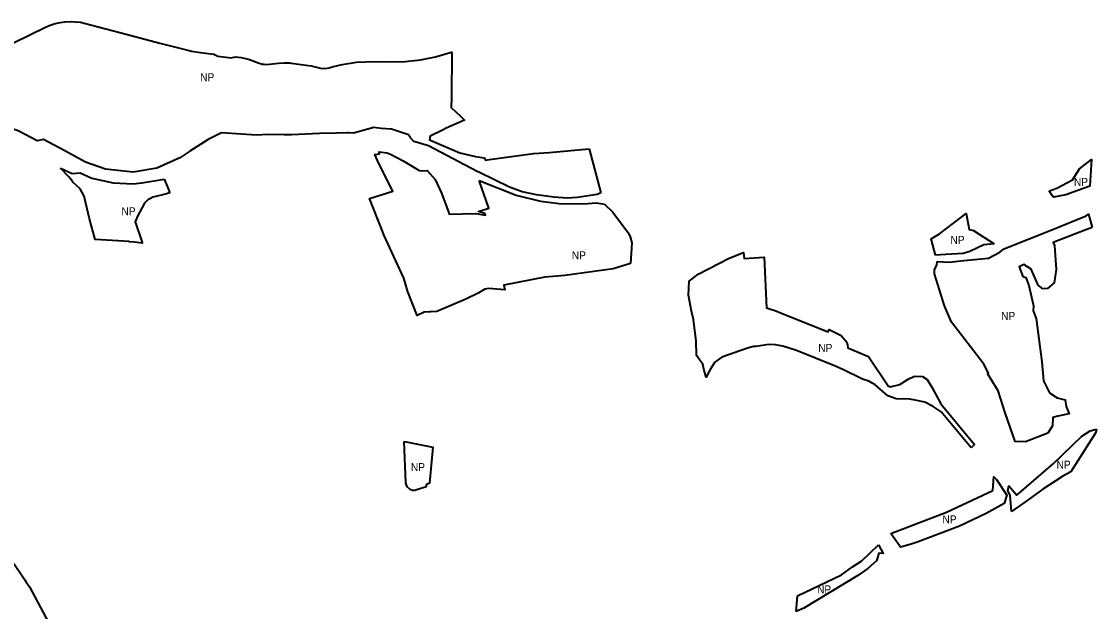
# Model space of a CAD drawing. Extents: x -650971 to -642489, y -1074311 to -1062745.
# Drawn here: x -645155 to -643544, y -1069701 to -1068817 of the extents above; entities that cross this region are included whole.
import ezdxf

# ---------------------------------------------------------------- set-up
doc = ezdxf.new("R2010")
doc.units = 0
doc.header["$LTSCALE"] = 4.8
for name, color, linetype, lineweight in [('24', 7, 'Continuous', 35), ('48', 7, 'Continuous', 35), ('62', 7, 'Continuous', 35)]:
    doc.layers.add(name, color=color, linetype=linetype, lineweight=lineweight)

msp = doc.modelspace()

# ---------------------------------------------------------------- linework, layer by layer
at = {"layer": '24'}
msp.add_lwpolyline([(-645166.67, -1069629), (-645153.33, -1069649.24), (-645150.3, -1069653.84), (-645148.8, -1069656.1), (-645143.56, -1069664.05), (-645118.98, -1069710.08), (-645095.1, -1069757.62), (-645063.26, -1069825.99), (-645051.78, -1069854.2), (-645043.5, -1069878.37), (-645032.85, -1069912.07), (-645024.45, -1069944.43), (-645018.28, -1069967.49)], dxfattribs=at)
at = {"layer": '48'}
for points in [[(-645212.72, -1068870.49), (-645119.5, -1068825.24), (-645112.38, -1068822.16), (-645104.87, -1068819.7), (-645097.47, -1068817.98), (-645090.01, -1068816.92), (-645082.34, -1068816.52), (-645074.66, -1068816.8), (-645067.04, -1068817.76), (-645059.46, -1068819.41), (-644998.7, -1068835.48), (-644947.96, -1068848.91), (-644906.18, -1068859.57), (-644900.37, -1068860.89), (-644883.44, -1068863.56), (-644867.05, -1068865.58), (-644861.04, -1068868.43), (-644840.86, -1068870.9), (-644834.48, -1068869.6), (-644826.24, -1068870.62), (-644819.79, -1068871.79), (-644813.52, -1068873.69), (-644799.27, -1068878.92), (-644795.57, -1068880.03), (-644794.33, -1068880.25), (-644791.66, -1068880.72), (-644787.7, -1068880.94), (-644783.84, -1068880.69), (-644770.17, -1068879.01), (-644761.63, -1068878.43), (-644753.71, -1068878.41), (-644751.36, -1068878.76), (-644721.29, -1068883.2), (-644707.32, -1068886.63), (-644700.83, -1068886.97), (-644694.39, -1068886.08), (-644689.63, -1068884.43), (-644674.5, -1068880.97), (-644653.09, -1068877.33), (-644626.34, -1068876.48), (-644602.97, -1068877.11), (-644580.06, -1068876.69), (-644557.21, -1068874.19), (-644534.67, -1068869.62), (-644512.71, -1068863.06), (-644510.37, -1068861.95)], [(-644510.37, -1068861.95), (-644510.75, -1068931.16), (-644511.47, -1068945.37), (-644503.61, -1068952.56), (-644498.8, -1068956.97), (-644496.63, -1068959.11), (-644491.31, -1068964.35), (-644514.16, -1068974.62), (-644519.61, -1068977.02), (-644523.4, -1068978.98), (-644543.05, -1068988.64), (-644544.02, -1068993.75), (-644498.28, -1069013.19), (-644475.09, -1069018.99), (-644461.74, -1069020.83), (-644459.67, -1069024.41), (-644453.95, -1069023.63), (-644387.91, -1069014.64), (-644364.53, -1069012.83), (-644304.6, -1069007.55)], [(-644952.47, -1069036.35), (-644988.11, -1069042.51), (-645029.47, -1069037.71), (-645059.3, -1069027.45), (-645090.35, -1069010.56), (-645122.25, -1068993.21), (-645131.73, -1068995.69), (-645159.37, -1068981.11), (-645189.84, -1068969.91), (-645218.85, -1068964.3), (-645232.4, -1068961.67), (-645255.21, -1068962.49), (-645275.45, -1068964.38), (-645292.77, -1068966.91), (-645311.99, -1068972.74), (-645328.55, -1068980.37), (-645350.17, -1068993.33), (-645371.56, -1069010.81), (-645396.53, -1069030.88), (-645413.29, -1069042.92)], [(-644803.31, -1068986.97), (-644855.56, -1068983.38), (-644875.57, -1068993.47), (-644903.21, -1069010.69), (-644918.04, -1069020.91), (-644952.47, -1069036.35)], [(-644657.61, -1068983.91), (-644665.41, -1068983.39), (-644667.57, -1068983.47), (-644683, -1068984.03), (-644708.6, -1068984.54), (-644750.67, -1068986.34), (-644761.88, -1068986.27), (-644785.78, -1068986.13), (-644803.31, -1068986.97)], [(-644572.05, -1068991.08), (-644575.29, -1068986.48), (-644600.67, -1068977.77), (-644616.36, -1068976.86), (-644627.41, -1068975.6), (-644657.61, -1068983.91)], [(-644286.94, -1069073.19), (-644292.27, -1069076.05), (-644319.2, -1069079.82), (-644322.55, -1069080.62), (-644337.6, -1069081.29), (-644357.4, -1069079.84), (-644383.55, -1069076.57), (-644404.96, -1069071.76), (-644424.01, -1069065.01), (-644468.95, -1069043.11), (-644472.37, -1069041.44), (-644545.54, -1069003.12), (-644567.09, -1068996.26), (-644572.05, -1068991.08)], [(-644614.41, -1069131.08), (-644633.66, -1069082), (-644598.81, -1069071.02), (-644619.54, -1069029.55), (-644625.69, -1069015.84), (-644618.8, -1069014.7), (-644619.1, -1069011.81), (-644607.16, -1069013.56), (-644601.43, -1069015.74), (-644583.05, -1069025.29), (-644563.19, -1069037.21), (-644558.56, -1069039.86), (-644553.62, -1069040.53), (-644547.31, -1069040.11), (-644535.13, -1069053.18), (-644525.83, -1069073.84), (-644515.07, -1069103.52), (-644514.47, -1069105.62), (-644474.33, -1069104.22), (-644459.82, -1069106.73), (-644461.01, -1069104.36), (-644470.37, -1069101.55), (-644454.75, -1069096.51), (-644469.28, -1069054.8)], [(-644304.6, -1069007.55), (-644293.51, -1069049.01), (-644286.94, -1069073.19)], [(-645096.97, -1069036.63), (-645079.65, -1069044.32), (-645067.65, -1069043.18), (-645049.91, -1069051.48), (-645017.77, -1069058.35), (-644987.99, -1069059.67), (-644975.19, -1069058.65), (-644941.27, -1069052.9)], [(-645080.589, -1069054.473), (-645084.19, -1069049.55), (-645096.97, -1069036.63)], [(-643614.82, -1069070.45), (-643614.36, -1069070.29), (-643603.72, -1069066.5), (-643580.21, -1069053.96), (-643569.44, -1069037.24), (-643551.72, -1069023.19), (-643554.17, -1069063.59)], [(-644932.95, -1069073.65), (-644943.69, -1069076.34), (-644958.25, -1069079.99), (-644962.15, -1069081.85), (-644965.95, -1069083.67), (-644970.84, -1069088.8), (-644981.3, -1069108.22), (-644985.15, -1069116.67), (-644974.34, -1069147.85), (-644974.505, -1069149.05), (-644986.221, -1069147.139), (-644994.006, -1069146.673), (-644993.99, -1069146.57), (-645044.97, -1069143.38), (-645053.61, -1069112.32), (-645061.2, -1069078.47), (-645067.57, -1069067.16), (-645078.47, -1069057.37), (-645080.589, -1069054.473)], [(-644941.27, -1069052.9), (-644937.05, -1069063.4), (-644932.95, -1069073.65)], [(-644469.28, -1069054.8), (-644414.04, -1069076.75), (-644377.36, -1069085.89), (-644349.32, -1069089.22), (-644331.44, -1069090), (-644306.29, -1069089.37), (-644293.62, -1069088.17), (-644281.26, -1069090.19)], [(-643554.17, -1069063.59), (-643589.94, -1069076.36), (-643608.65, -1069080.11), (-643610.31, -1069077.52), (-643614.82, -1069070.45)], [(-644281.26, -1069090.19), (-644269.11, -1069102.31), (-644245.65, -1069133.66), (-644243.14, -1069139.47), (-644240.67, -1069148.58), (-644242.48, -1069179.49)], [(-643785.6, -1069166.98), (-643792.04, -1069142.27), (-643784.55, -1069137.77), (-643779.31, -1069134.63), (-643747.75, -1069110.71), (-643739.66, -1069104.58), (-643734.75, -1069128.3), (-643728.49, -1069129.95), (-643697.29, -1069149.7)], [(-643782.92, -1069176.24), (-643764.86, -1069177.58), (-643743.11, -1069175.08), (-643705.7, -1069171.37), (-643688.91, -1069162.16), (-643683.68, -1069157.86), (-643681.63, -1069157.04), (-643610.81, -1069129.04), (-643559.5, -1069107.98), (-643555.98, -1069105.57), (-643550.79, -1069125.24)], [(-644470.64, -1069224), (-644489.27, -1069233.04), (-644532.71, -1069251.12), (-644541.83, -1069251.66), (-644543.88, -1069251.78), (-644552.01, -1069252.24), (-644562.47, -1069257.56), (-644576.08, -1069221.66), (-644582.29, -1069201.27), (-644612.3, -1069136.45), (-644614.41, -1069131.08)], [(-643550.79, -1069125.24), (-643559.88, -1069129.05), (-643609.08, -1069147.64), (-643607.02, -1069152.34)], [(-643697.29, -1069149.7), (-643712.74, -1069151.46), (-643733.83, -1069161.46), (-643743.99, -1069164.43), (-643769.71, -1069166.04), (-643785.6, -1069166.98)], [(-644143.54, -1069317.05), (-644144.05, -1069295.67), (-644148.22, -1069263.22), (-644151.11, -1069250.7), (-644155.37, -1069226.72), (-644154.36, -1069206.06), (-644141.24, -1069195.17), (-644094.79, -1069171.27), (-644073.35, -1069162.84), (-644071.97, -1069171.72), (-644042.37, -1069169.77), (-644038.83, -1069245.65), (-644024.93, -1069250.23), (-644015.12, -1069254.24), (-643946.16, -1069281.84), (-643944.89, -1069278.32), (-643926.74, -1069287.37), (-643918.08, -1069297.33), (-643917.36, -1069302.04), (-643916.78, -1069305.89), (-643885.63, -1069318.72), (-643856.43, -1069362.68), (-643853.56, -1069364.44), (-643838.69, -1069360.79), (-643826.21, -1069352.92), (-643817.06, -1069348.14), (-643804.83, -1069348.99), (-643798.1, -1069353.51), (-643791.02, -1069364.54), (-643777.27, -1069389.71), (-643726.74, -1069450.72), (-643731.98, -1069455.66)], [(-643607.02, -1069152.34), (-643604.38, -1069188.48), (-643607.37, -1069208.43), (-643617.64, -1069217), (-643624.38, -1069217.27), (-643631.66, -1069211.67), (-643641.84, -1069187.68), (-643653.05, -1069180.98), (-643660.22, -1069184.11), (-643654.57, -1069198.77), (-643649.84, -1069200.4), (-643645.61, -1069212.25), (-643638.72, -1069242.94), (-643639.23, -1069250.38), (-643634.56, -1069262.02), (-643625.9, -1069326.77), (-643623.28, -1069355.47), (-643614.35, -1069373.28), (-643602.92, -1069380.53), (-643590.89, -1069383.9), (-643589.52, -1069393.88), (-643585.19, -1069404.76), (-643601.9, -1069408.43), (-643609.6, -1069409.99), (-643610.18, -1069422.91), (-643616.78, -1069433.81), (-643650.28, -1069446.91), (-643665.87, -1069446.1), (-643681.09, -1069403.24), (-643691.6, -1069370.3), (-643707.23, -1069344.52)], [(-644242.48, -1069179.49), (-644268.7, -1069187.42), (-644340.83, -1069197.13), (-644371.08, -1069199.84), (-644432.53, -1069212.02), (-644430.91, -1069218.82), (-644454.87, -1069217.05), (-644460.97, -1069217.61), (-644470.64, -1069224)], [(-643707.23, -1069344.52), (-643705.74, -1069343.54), (-643712.78, -1069330.24), (-643761.21, -1069267.12), (-643771.86, -1069242.77), (-643786.89, -1069195.02), (-643786.97, -1069188.11), (-643783.2, -1069181.85), (-643782.92, -1069176.24)], [(-643731.98, -1069455.66), (-643776.78, -1069401.87), (-643788.63, -1069393.7), (-643801.36, -1069387.23), (-643815.93, -1069384.23), (-643823.72, -1069382.61), (-643844.28, -1069382.26), (-643856.58, -1069377.59), (-643876.34, -1069360.61), (-643879.48, -1069359.13), (-643885.22, -1069355.58), (-643894.84, -1069352.76), (-643924.42, -1069338.29), (-643936.87, -1069332.93), (-643993.91, -1069309.57), (-644014.19, -1069303.36), (-644025.24, -1069301.38), (-644035.89, -1069301.02), (-644054.35, -1069303.55), (-644058.05, -1069304.02), (-644067.08, -1069306.15), (-644105.5, -1069320.03), (-644116.33, -1069327.36), (-644123.21, -1069338.41), (-644129.09, -1069349.83), (-644132.52, -1069338.02), (-644134.15, -1069330.45), (-644138.55, -1069324.23), (-644143.54, -1069317.05)], [(-643676.9, -1069519.91), (-643675.32, -1069512.62), (-643663.46, -1069526.87), (-643608.89, -1069479.72), (-643565.92, -1069438.4), (-643553.7, -1069430.44), (-643544.06, -1069427.6)], [(-643544.06, -1069427.6), (-643545.07, -1069432.89), (-643582.77, -1069491.76)], [(-644581.87, -1069446.28), (-644578.92, -1069446.8), (-644539, -1069454.88), (-644543.99, -1069508.88), (-644548.63, -1069511.41), (-644548.78, -1069514.21)], [(-644548.78, -1069514.21), (-644561.24, -1069518.27), (-644566.01, -1069519.75), (-644569.16, -1069519.63), (-644572.75, -1069518.39), (-644577.16, -1069514.36), (-644579.1, -1069508.42), (-644581.87, -1069446.28)], [(-643699.23, -1069519.48), (-643697.85, -1069499.21), (-643693.95, -1069503.38), (-643678.24, -1069526.44), (-643682.27, -1069539.41)], [(-643582.77, -1069491.76), (-643594.49, -1069498.17), (-643605.97, -1069505.47), (-643624.65, -1069517.85), (-643649.94, -1069535.93), (-643671.53, -1069551.1)], [(-643852.51, -1069584.08), (-643769.08, -1069551.96), (-643699.23, -1069519.48)], [(-643671.53, -1069551.1), (-643673.34, -1069527.08), (-643676.9, -1069519.91)], [(-643682.27, -1069539.41), (-643709.33, -1069554.14), (-643749.64, -1069573.35)], [(-643749.64, -1069573.35), (-643811.16, -1069596.45), (-643822.06, -1069600.07), (-643837.72, -1069604.62), (-643852.51, -1069584.08)], [(-643994.36, -1069701.05), (-643992.34, -1069677.76), (-643926.229, -1069646.367), (-643909.616, -1069634.267), (-643895.951, -1069625.069), (-643870.697, -1069601.241)], [(-643870.697, -1069601.241), (-643863.92, -1069613.9), (-643870.44, -1069613.56), (-643872.55, -1069620.75), (-643873.82, -1069625.05), (-643886.62, -1069636.87), (-643901.55, -1069646.92), (-643982.84, -1069695.93), (-643994.36, -1069701.05)]]:
    msp.add_lwpolyline(points, dxfattribs=at)

# ---------------------------------------------------------------- texts
at = {"layer": '62', "width": 0.95}
for p in [(-644887.583, -1068906.041), (-643577.985, -1069062.967), (-645005.583, -1069107.041), (-643762.985, -1069149.967), (-644330.583, -1069173.041), (-643686.985, -1069263.967), (-643961.069, -1069311.925), (-644571.689, -1069490.616), (-643603.985, -1069486.967), (-643774.985, -1069568.967), (-643962.985, -1069673.967)]:
    msp.add_text('NP', height=12, dxfattribs=at).set_placement(p)

doc.saveas('drawing.dxf')
